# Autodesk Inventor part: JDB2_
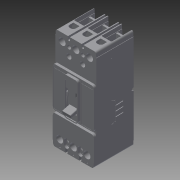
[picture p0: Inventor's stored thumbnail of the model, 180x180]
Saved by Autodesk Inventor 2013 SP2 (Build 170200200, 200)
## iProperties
Created: 2014-08
Part Number: JDB2_
Material: Generic
Document SubType Name: Modeling
Designer: EM/EM
Density: 1 g/cm^3
Description: TYPE JDB THERMAL MAGNETIC CIRCUIT BREAKERS TWO POLE, SERIES C
MXEDIT: false
MXINVTNRV: INV Versioned Component|JDB2_|004.0
Author: EM/EM
Revision Number: 004
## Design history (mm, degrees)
derived "JD2_.iam"
node "L1"
node "L2"
node "T1"
node "T2"
sketch "Sketch1"
  geometry: C1 r 10.795 at (8.89, 11.913) reference; C2 r 10.795 at (8.89, 11.913); 1 further point
  constraints: 1 centre point, 1 coincident, 1 concentric
extrude "Extrusion1" cut sketch "Sketch1" distance "d1" = 9.525; taper "d2" = 0 deg
sketch "Sketch2"
  geometry: C1 r 6.35 at (0, 0) reference; C2 r 6.35 at (0, 0); 1 further point
  constraints: 1 centre point, 1 coincident, 1 concentric
extrude "Extrusion2" cut sketch "Sketch2" distance "d3" = 9.525; taper "d5" = 0 deg; dims "d4" = 4.7752, "d6" = 0
sketch "Sketch3"
  geometry: C1 r 10.795 at (11.493, 11.913) reference; C2 r 10.795 at (11.493, 11.913); 1 further point
  constraints: 1 centre point, 1 coincident, 1 concentric
extrude "Extrusion3" cut sketch "Sketch3" distance "d7" = 9.525; taper "d8" = 0 deg
sketch "Sketch4"
  geometry: C1 r 6.35 at (0, 0) reference; C2 r 6.35 at (0, 0); 1 further point
  constraints: 1 centre point, 1 coincident, 1 concentric
extrude "Extrusion4" cut sketch "Sketch4" distance "d9" = 9.525; taper "d11" = 0 deg; dims "d10" = 4.7752, "d12" = 0
sketch "Sketch5"
  geometry: C1 r 8.738 at (34.912, 0) reference; C2 r 8.738 at (34.912, 0); 1 further point
  constraints: 1 centre point, 1 coincident, 1 concentric
extrude "Extrusion5" cut sketch "Sketch5" distance "d13" = 9.525; taper "d15" = 0 deg; dims "d14" = 4.7752, "d16" = 0
sketch "Sketch6"
  geometry: C1 r 8.738 at (-34.938, 0) reference; C2 r 8.738 at (-34.938, 0); 1 further point
  constraints: 1 centre point, 1 coincident, 1 concentric
extrude "Extrusion6" cut sketch "Sketch6" distance "d17" = 9.525; taper "d19" = 0 deg; dims "d18" = 4.7752, "d20" = 0
body "Solid1"
node "JD2_.ipt:1"
